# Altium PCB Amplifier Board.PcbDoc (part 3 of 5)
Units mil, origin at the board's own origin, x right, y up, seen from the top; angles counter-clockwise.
Board outline 6000 x 4000 mil, 6 copper layers (Top Layer, GND, VCC, InternalPlane3, InternalPlane4, Bottom Layer); 880 components, 519 nets, 2020 pads, 372 vias.
Unrouted connection lines stored in the file: 585.
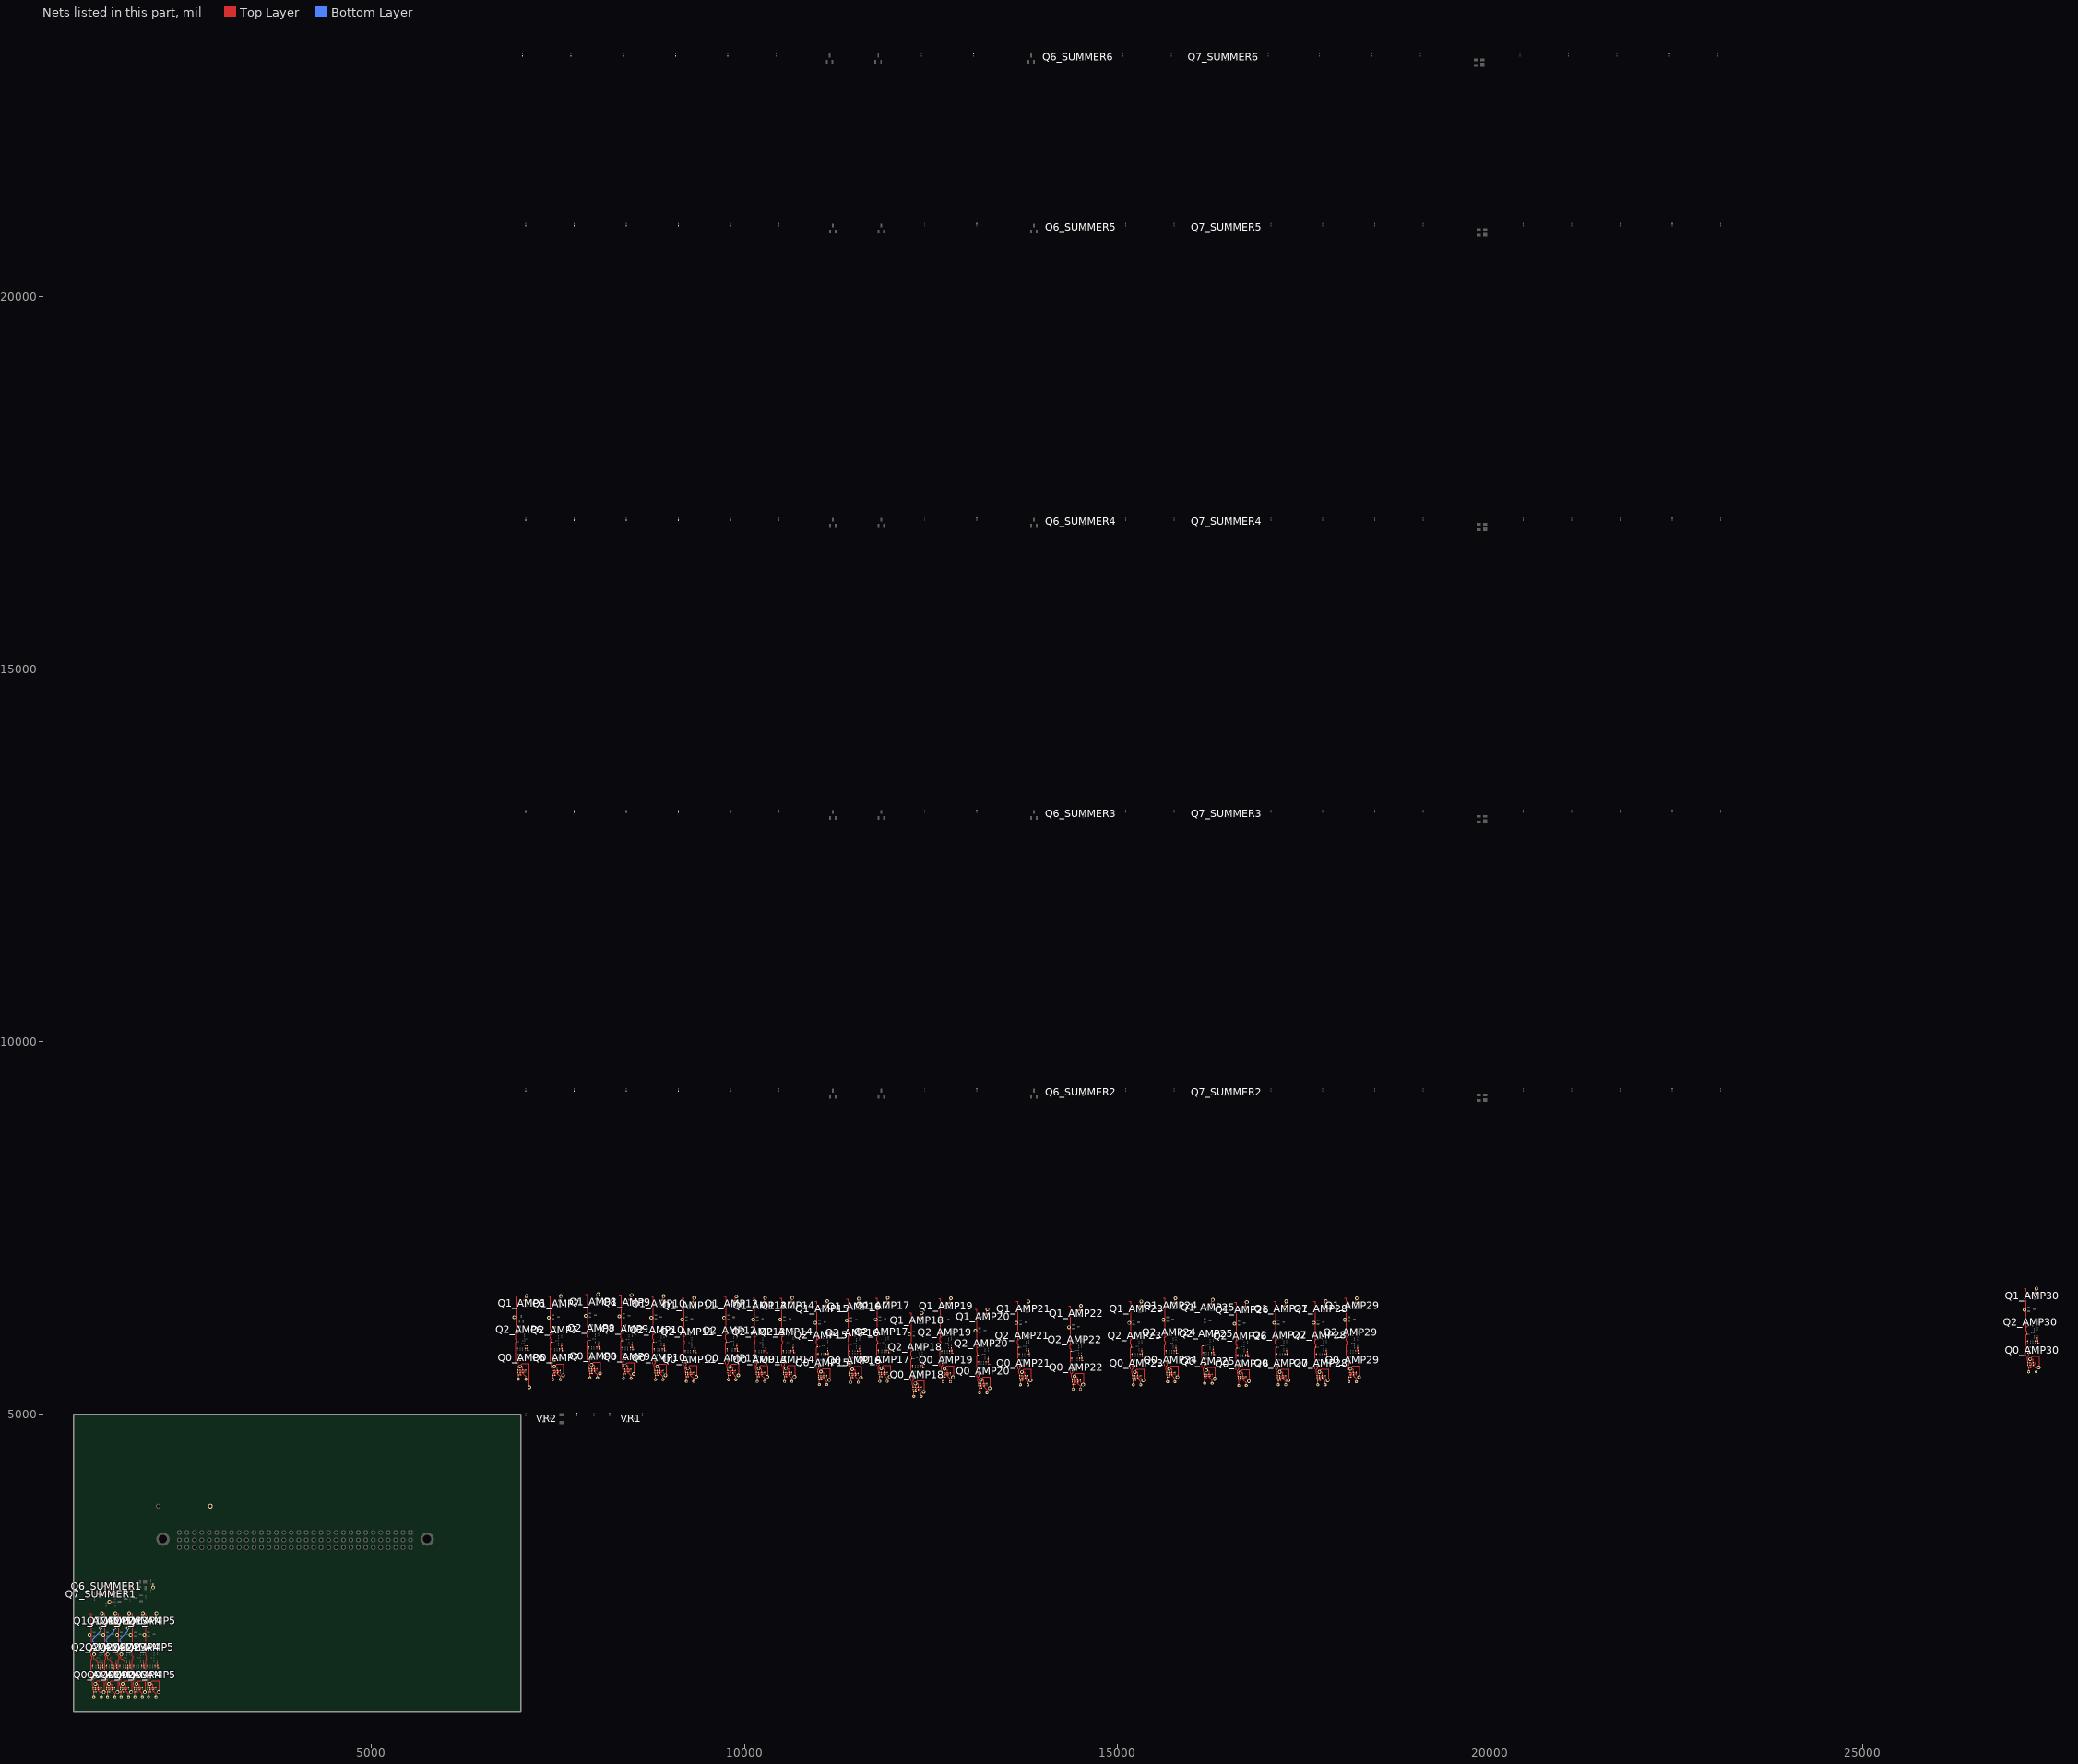
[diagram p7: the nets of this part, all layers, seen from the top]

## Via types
v1: diameter 50, hole 28, Top Layer to Bottom Layer, 371 vias
v2: diameter 50, hole 28, Top Layer to Bottom Layer, tented top, 1 vias

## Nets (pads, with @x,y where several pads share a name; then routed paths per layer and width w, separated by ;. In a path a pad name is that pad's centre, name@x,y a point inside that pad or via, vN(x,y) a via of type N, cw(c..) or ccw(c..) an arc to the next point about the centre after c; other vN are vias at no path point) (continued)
GND: C1_AMP1.2 C1_AMP2.2 C1_AMP3.2 C1_AMP4.2 C1_AMP5.2 C1_AMP6.2 C1_AMP7.2 C1_AMP8.2 C1_AMP9.2 C1_AMP10.2 C1_AMP11.2 C1_AMP12.2 C1_AMP13.2 C1_AMP14.2 C1_AMP15.2 C1_AMP16.2 C1_AMP17.2 C1_AMP18.2 C1_AMP19.2 C1_AMP20.2 C1_AMP21.2 C1_AMP22.2 C1_AMP23.2 C1_AMP24.2 C1_AMP25.2 C1_AMP26.2 C1_AMP27.2 C1_AMP28.2 C1_AMP29.2 C1_AMP30.2 C3_AMP1.1 C3_AMP2.1 C3_AMP3.1 C3_AMP4.1 C3_AMP5.1 C3_AMP6.1 C3_AMP7.1 C3_AMP8.1 C3_AMP9.1 C3_AMP10.1 C3_AMP11.1 C3_AMP12.1 C3_AMP13.1 C3_AMP14.1 C3_AMP15.1 C3_AMP16.1 C3_AMP17.1 C3_AMP18.1 C3_AMP19.1 C3_AMP20.1 C3_AMP21.1 C3_AMP22.1 C3_AMP23.1 C3_AMP24.1 C3_AMP25.1 C3_AMP26.1 C3_AMP27.1 C3_AMP28.1 C3_AMP29.1 C3_AMP30.1 CBi_AMP1.2 CBi_AMP2.2 CBi_AMP3.2 CBi_AMP4.2 CBi_AMP5.2 CBi_AMP6.2 CBi_AMP7.2 CBi_AMP8.2 CBi_AMP9.2 CBi_AMP10.2 CBi_AMP11.2 CBi_AMP12.2 CBi_AMP13.2 CBi_AMP14.2 CBi_AMP15.2 CBi_AMP16.2 CBi_AMP17.2 CBi_AMP18.2 CBi_AMP19.2 CBi_AMP20.2 CBi_AMP21.2 CBi_AMP22.2 CBi_AMP23.2 CBi_AMP24.2 CBi_AMP25.2 CBi_AMP26.2 CBi_AMP27.2 CBi_AMP28.2 CBi_AMP29.2 CBi_AMP30.2 CBi_SUMMER1.2 CBi_SUMMER2.2 CBi_SUMMER3.2 CBi_SUMMER4.2 CBi_SUMMER5.2 CBi_SUMMER6.2 CG_SUMMER1.2 CG_SUMMER2.2 CG_SUMMER3.2 CG_SUMMER4.2 CG_SUMMER5.2 CG_SUMMER6.2 D1.1 Q1_AMP1.2 Q1_AMP2.2 Q1_AMP3.2 Q1_AMP4.2 Q1_AMP5.2 Q1_AMP6.2 Q1_AMP7.2 Q1_AMP8.2 Q1_AMP9.2 Q1_AMP10.2 Q1_AMP11.2 Q1_AMP12.2 Q1_AMP13.2 Q1_AMP14.2 Q1_AMP15.2 Q1_AMP16.2 Q1_AMP17.2 Q1_AMP18.2 Q1_AMP19.2 Q1_AMP20.2 Q1_AMP21.2 Q1_AMP22.2 Q1_AMP23.2 Q1_AMP24.2 Q1_AMP25.2 Q1_AMP26.2 Q1_AMP27.2 Q1_AMP28.2 Q1_AMP29.2 Q1_AMP30.2 Q2_AMP1.3 Q2_AMP2.3 Q2_AMP3.3 Q2_AMP4.3 Q2_AMP5.3 Q2_AMP6.3 Q2_AMP7.3 Q2_AMP8.3 Q2_AMP9.3 Q2_AMP10.3 Q2_AMP11.3 Q2_AMP12.3 Q2_AMP13.3 Q2_AMP14.3 Q2_AMP15.3 Q2_AMP16.3 Q2_AMP17.3 Q2_AMP18.3 Q2_AMP19.3 Q2_AMP20.3 Q2_AMP21.3 Q2_AMP22.3 Q2_AMP23.3 Q2_AMP24.3 Q2_AMP25.3 Q2_AMP26.3 Q2_AMP27.3 Q2_AMP28.3 Q2_AMP29.3 Q2_AMP30.3 Q6_SUMMER1.3 Q6_SUMMER2.3 Q6_SUMMER3.3 Q6_SUMMER4.3 Q6_SUMMER5.3 Q6_SUMMER6.3 Q7_SUMMER1.3 Q7_SUMMER2.3 Q7_SUMMER3.3 Q7_SUMMER4.3 Q7_SUMMER5.3 Q7_SUMMER6.3 R1_AMP1.1 R1_AMP2.1 R1_AMP3.1 R1_AMP4.1 R1_AMP5.1 R1_AMP6.1 R1_AMP7.1 R1_AMP8.1 R1_AMP9.1 R1_AMP10.1 R1_AMP11.1 R1_AMP12.1 R1_AMP13.1 R1_AMP14.1 R1_AMP15.1 R1_AMP16.1 R1_AMP17.1 R1_AMP18.1 R1_AMP19.1 R1_AMP20.1 R1_AMP21.1 R1_AMP22.1 R1_AMP23.1 R1_AMP24.1 R1_AMP25.1 R1_AMP26.1 R1_AMP27.1 R1_AMP28.1 R1_AMP29.1 R1_AMP30.1 R3_AMP1.1 R3_AMP2.1 R3_AMP3.1 R3_AMP4.1 R3_AMP5.1 R3_AMP6.1 R3_AMP7.1 R3_AMP8.1 R3_AMP9.1 R3_AMP10.1 R3_AMP11.1 R3_AMP12.1 R3_AMP13.1 R3_AMP14.1 R3_AMP15.1 R3_AMP16.1 R3_AMP17.1 R3_AMP18.1 R3_AMP19.1 R3_AMP20.1 R3_AMP21.1 R3_AMP22.1 R3_AMP23.1 R3_AMP24.1 R3_AMP25.1 R3_AMP26.1 R3_AMP27.1 R3_AMP28.1 R3_AMP29.1 R3_AMP30.1 R9_SUMMER1.1 R9_SUMMER2.1 R9_SUMMER3.1 R9_SUMMER4.1 R9_SUMMER5.1 R9_SUMMER6.1 R12_SUMMER1.1 R12_SUMMER2.1 R12_SUMMER3.1 R12_SUMMER4.1 R12_SUMMER5.1 R12_SUMMER6.1 R14_SUMMER1.1 R14_SUMMER2.1 R14_SUMMER3.1 R14_SUMMER4.1 R14_SUMMER5.1 R14_SUMMER6.1 R17_SUMMER1.1 R17_SUMMER2.1 R17_SUMMER3.1 R17_SUMMER4.1 R17_SUMMER5.1 R17_SUMMER6.1 R19_AMP1.1 R19_AMP2.1 R19_AMP3.1 R19_AMP4.1 R19_AMP5.1 R19_AMP6.1 R19_AMP7.1 R19_AMP8.1 R19_AMP9.1 R19_AMP10.1 R19_AMP11.1 R19_AMP12.1 R19_AMP13.1 R19_AMP14.1 R19_AMP15.1 R19_AMP16.1 R19_AMP17.1 R19_AMP18.1 R19_AMP19.1 R19_AMP20.1 R19_AMP21.1 R19_AMP22.1 R19_AMP23.1 R19_AMP24.1 R19_AMP25.1 R19_AMP26.1 R19_AMP27.1 R19_AMP28.1 R19_AMP29.1 R19_AMP30.1 R22.2 R24.2 RC_SUMMER1.1 RC_SUMMER2.1 RC_SUMMER3.1 RC_SUMMER4.1 RC_SUMMER5.1 RC_SUMMER6.1 VR1.2 VR2.2 | length 48068.1
  Top Layer w7: 1216,2328 1242,2328 1242,1815 1241,1814 ; v1@1228,2039 v1@1241,2039 ; 1238,1420 1238,1701.78 R3_AMP1.1@1250.22,1714 ; 1238.22,1623.78 CBi_AMP1.2@1259,1623.78 ; R3_AMP1.1@1249,1715.22 1249,1745 1237.5,1756.5 1237.5,1806.5 1241,1814 ; 1275.41,1838.57 1250.84,1814 1241,1814 ; R19_AMP1.1@1302.78,1269 1302.78,1280.22 1294,1289 R1_AMP1.1@1294,1304 1314.59,1304 1314.59,1328.37 1317.78,1331.56 C1_AMP1.2@1334,1331.56 1334,1371.56 1324,1381.56 v1(1294,1381.56) 1294,1391 1324,1421 1419,1421 1419,1280 v1(1408,1269) ; Q1_AMP1.2@1370.34,2266.4 1370.34,2317.34 v1(1381,2328) ; C3_AMP1.1@1395,1596.22 1417.22,1596.22 ; v1@1399,2328 1425,2328 1425,1815 1424,1814 ; 1410.43,2559.41 1421.41,2559.41 1463,2601 v1(1543,2601) ; v1@1411,2039 v1@1424,2039 ; 1421,1420 1421,1701.78 R3_AMP2.1@1433.22,1714 ; 1421.22,1623.78 CBi_AMP2.2@1442,1623.78 ; R3_AMP2.1@1432,1715.22 1432,1745 1420.5,1756.5 1420.5,1806.5 1424,1814 ; R9_SUMMER1.1@1435,2453.78 1453.78,2453.78 v1(1484,2484) R12_SUMMER1.1@1535.22,2484 ; 1458.41,1838.57 1433.84,1814 1424,1814 ; 1480.43,2664.41 1480.43,2656.32 1498.54,2638.22 RC_SUMMER1.1@1524,2638.22 1524,2620 v1(1543,2601) ; R19_AMP2.1@1485.78,1269 1485.78,1280.22 1477,1289 R1_AMP2.1@1477,1304 1497.59,1304 1497.59,1328.37 1500.78,1331.56 C1_AMP2.2@1517,1331.56 1517,1371.56 1507,1381.56 v1(1477,1381.56) 1477,1391 1507,1421 1602,1421 1602,1280 v1(1591,1269) ; CBi_SUMMER1.2@1536.22,2555 1536.22,2594.22 v1(1543,2601) ; Q1_AMP2.2@1553.34,2266.4 1553.34,2317.34 v1(1564,2328) ; C3_AMP2.1@1578,1596.22 1600.22,1596.22 ; v1@1582,2328 1608,2328 1608,1815 1607,1814 ; v1@1594,2039 v1@1607,2039 ; 1604,1420 1604,1701.78 R3_AMP3.1@1616.22,1714 ; 1604.22,1623.78 CBi_AMP3.2@1625,1623.78 ; R3_AMP3.1@1615,1715.22 1615,1745 1603.5,1756.5 1603.5,1806.5 1607,1814 ; 1641.41,1838.57 1616.84,1814 1607,1814 ; R19_AMP3.1@1668.78,1269 1668.78,1280.22 1660,1289 R1_AMP3.1@1660,1304 1680.59,1304 1680.59,1328.37 1683.78,1331.56 C1_AMP3.2@1700,1331.56 1700,1371.56 1690,1381.56 v1(1660,1381.56) 1660,1391 1690,1421 1785,1421 1785,1280 v1(1774,1269) ; Q1_AMP3.2@1736.34,2266.4 1736.34,2317.34 v1(1747,2328) ; C3_AMP3.1@1761,1596.22 1783.22,1596.22 ; v1@1766,2328 1792,2328 1792,1815 1791,1814 ; R17_SUMMER1.1@1777.78,2627 R14_SUMMER1.1@1777.78,2702 ; v1@1778,2039 v1@1791,2039 ; 1788,1420 1788,1701.78 R3_AMP4.1@1800.22,1714 ; 1788.22,1623.78 CBi_AMP4.2@1809,1623.78 ; R3_AMP4.1@1799,1715.22 1799,1745 1787.5,1756.5 1787.5,1806.5 1791,1814 ; 1825.41,1838.57 1800.84,1814 1791,1814 ; R19_AMP4.1@1852.78,1269 1852.78,1280.22 1844,1289 R1_AMP4.1@1844,1304 1864.59,1304 1864.59,1328.37 1867.78,1331.56 C1_AMP4.2@1884,1331.56 1884,1371.56 1874,1381.56 v1(1844,1381.56) 1844,1391 1874,1421 1969,1421 1969,1280 v1(1958,1269) ; Q1_AMP4.2@1920.34,2266.4 1920.34,2317.34 v1(1931,2328) ; C3_AMP4.1@1945,1596.22 1967.22,1596.22 ; v1@1949,2328 1975,2328 1975,1815 1974,1814 ; v1@1961,2039 v1@1974,2039 ; 1971,1420 1971,1701.78 R3_AMP5.1@1983.22,1714 ; 1971.22,1623.78 CBi_AMP5.2@1992,1623.78 ; R3_AMP5.1@1982,1715.22 1982,1745 1970.5,1756.5 1970.5,1806.5 1974,1814 ; 2008.41,1838.57 1983.84,1814 1974,1814 ; R19_AMP5.1@2035.78,1269 2035.78,1280.22 2027,1289 R1_AMP5.1@2027,1304 2047.59,1304 2047.59,1328.37 2050.78,1331.56 C1_AMP5.2@2067,1331.56 2067,1371.56 2057,1381.56 v1(2027,1381.56) 2027,1391 2057,1421 2152,1421 2152,1280 v1(2141,1269) ; v1@2068.78,2675.22 CG_SUMMER1.2@2068.78,2720 ; Q1_AMP5.2@2103.34,2266.4 2103.34,2317.34 v1(2114,2328) ; C3_AMP5.1@2128,1596.22 2150.22,1596.22 ; 6912,6588 6938,6588 6938,6075 6937,6074 6933.5,6066.5 6933.5,6000 6945,5988.5 R3_AMP6.1@6945,5975.22 ; v1@6924,6299 v1@6937,6299 ; 6934,5680 6934,5961.78 R3_AMP6.1@6946.22,5974 ; 6934.22,5883.78 CBi_AMP6.2@6955,5883.78 ; 6940.57,6170.43 Q2_AMP6.3@6988,6170.43 ; R19_AMP6.1@6998.78,5529 6998.78,5540.22 6990,5549 R1_AMP6.1@6990,5564 7010.59,5564 7010.59,5588.37 7013.78,5591.56 C1_AMP6.2@7030,5591.56 7030,5631.56 7020,5641.56 v1(6990,5641.56) 6990,5651 7020,5681 7115,5681 v2@7115,5361 ; Q1_AMP6.2@7066.34,6526.4 7066.34,6577.34 v1(7077,6588) ; C3_AMP6.1@7091,5856.22 7113.22,5856.22 ; 7374,6583 7400,6583 7400,6070 7399,6069 ; v1@7386,6294 v1@7399,6294 ; 7396,5675 7396,5956.78 R3_AMP7.1@7408.22,5969 ; 7396.22,5878.78 CBi_AMP7.2@7417,5878.78 ; R3_AMP7.1@7407,5970.22 7407,6000 7395.5,6011.5 7395.5,6061.5 7399,6069 ; 7433.41,6093.57 7408.84,6069 7399,6069 ; R19_AMP7.1@7460.78,5524 7460.78,5535.22 7452,5544 R1_AMP7.1@7452,5559 7472.59,5559 7472.59,5583.37 7475.78,5586.56 C1_AMP7.2@7492,5586.56 7492,5626.56 7482,5636.56 v1(7452,5636.56) 7452,5646 7482,5676 7577,5676 7577,5535 v1(7566,5524) ; Q1_AMP7.2@7528.34,6521.4 7528.34,6572.34 v1(7539,6583) ; C3_AMP7.1@7553,5851.22 7575.22,5851.22 ; 7871,6607 7897,6607 7897,6094 7896,6093 ; v1@7883,6318 v1@7896,6318 ; 7893,5699 7893,5980.78 R3_AMP8.1@7905.22,5993 ; 7893.22,5902.78 CBi_AMP8.2@7914,5902.78 ; R3_AMP8.1@7904,5994.22 7904,6024 7892.5,6035.5 7892.5,6085.5 7896,6093 ; 7930.41,6117.57 7905.84,6093 7896,6093 ; R19_AMP8.1@7957.78,5548 7957.78,5559.22 7949,5568 R1_AMP8.1@7949,5583 7969.59,5583 7969.59,5607.37 7972.78,5610.56 C1_AMP8.2@7989,5610.56 7989,5650.56 7979,5660.56 v1(7949,5660.56) 7949,5670 7979,5700 8074,5700 8074,5559 v1(8063,5548) ; Q1_AMP8.2@8025.34,6545.4 8025.34,6596.34 v1(8036,6607) ; C3_AMP8.1@8050,5875.22 8072.22,5875.22 ; 8322,6600 8348,6600 8348,6087 8347,6086 ; v1@8334,6311 v1@8347,6311 ; 8344,5692 8344,5973.78 R3_AMP9.1@8356.22,5986 ; 8344.22,5895.78 CBi_AMP9.2@8365,5895.78 ; R3_AMP9.1@8355,5987.22 8355,6017 8343.5,6028.5 8343.5,6078.5 8347,6086 ; 8381.41,6110.57 8356.84,6086 8347,6086 ; R19_AMP9.1@8408.78,5541 8408.78,5552.22 8400,5561 R1_AMP9.1@8400,5576 8420.59,5576 8420.59,5600.37 8423.78,5603.56 C1_AMP9.2@8440,5603.56 8440,5643.56 8430,5653.56 v1(8400,5653.56) 8400,5663 8430,5693 8525,5693 8525,5552 v1(8514,5541) ; Q1_AMP9.2@8476.34,6538.4 8476.34,6589.34 v1(8487,6600) ; C3_AMP9.1@8501,5868.22 8523.22,5868.22 ; 8751,6583 8777,6583 8777,6070 8776,6069 ; v1@8763,6294 v1@8776,6294 ; 8773,5675 8773,5956.78 R3_AMP10.1@8785.22,5969 ; 8773.22,5878.78 CBi_AMP10.2@8794,5878.78 ; R3_AMP10.1@8784,5970.22 8784,6000 8772.5,6011.5 8772.5,6061.5 8776,6069 ; 8810.41,6093.57 8785.84,6069 8776,6069 ; R19_AMP10.1@8837.78,5524 8837.78,5535.22 8829,5544 R1_AMP10.1@8829,5559 8849.59,5559 8849.59,5583.37 8852.78,5586.56 C1_AMP10.2@8869,5586.56 8869,5626.56 8859,5636.56 v1(8829,5636.56) 8829,5646 8859,5676 8954,5676 8954,5535 v1(8943,5524) ; Q1_AMP10.2@8905.34,6521.4 8905.34,6572.34 v1(8916,6583) ; C3_AMP10.1@8930,5851.22 8952.22,5851.22 ; 9163,6559 9189,6559 9189,6046 9188,6045 ; v1@9175,6270 v1@9188,6270 ; 9185,5651 9185,5932.78 R3_AMP11.1@9197.22,5945 ; 9185.22,5854.78 CBi_AMP11.2@9206,5854.78 ; R3_AMP11.1@9196,5946.22 9196,5976 9184.5,5987.5 9184.5,6037.5 9188,6045 ; 9222.41,6069.57 9197.84,6045 9188,6045 ; R19_AMP11.1@9249.78,5500 9249.78,5511.22 9241,5520 R1_AMP11.1@9241,5535 9261.59,5535 9261.59,5559.37 9264.78,5562.56 C1_AMP11.2@9281,5562.56 9281,5602.56 9271,5612.56 v1(9241,5612.56) 9241,5622 9271,5652 9366,5652 9366,5511 v1(9355,5500) ; Q1_AMP11.2@9317.34,6497.4 9317.34,6548.34 v1(9328,6559) ; C3_AMP11.1@9342,5827.22 9364.22,5827.22 ; 9727,6581 9753,6581 9753,6068 9752,6067 ; v1@9739,6292 v1@9752,6292 ; 9749,5673 9749,5954.78 R3_AMP12.1@9761.22,5967 ; 9749.22,5876.78 CBi_AMP12.2@9770,5876.78 ; R3_AMP12.1@9760,5968.22 9760,5998 9748.5,6009.5 9748.5,6059.5 9752,6067 ; 9786.41,6091.57 9761.84,6067 9752,6067 ; R19_AMP12.1@9813.78,5522 9813.78,5533.22 9805,5542 R1_AMP12.1@9805,5557 9825.59,5557 9825.59,5581.37 9828.78,5584.56 C1_AMP12.2@9845,5584.56 9845,5624.56 9835,5634.56 v1(9805,5634.56) 9805,5644 9835,5674 9930,5674 9930,5533 v1(9919,5522) ; Q1_AMP12.2@9881.34,6519.4 9881.34,6570.34 v1(9892,6581) ; C3_AMP12.1@9906,5849.22 9928.22,5849.22 ; 10114,6559 10140,6559 10140,6046 10139,6045 ; v1@10126,6270 v1@10139,6270 ; 10136,5651 10136,5932.78 R3_AMP13.1@10148.22,5945 ; 10136.22,5854.78 CBi_AMP13.2@10157,5854.78 ; R3_AMP13.1@10147,5946.22 10147,5976 10135.5,5987.5 10135.5,6037.5 10139,6045 ; 10173.41,6069.57 10148.84,6045 10139,6045 ; R19_AMP13.1@10200.78,5500 10200.78,5511.22 10192,5520 R1_AMP13.1@10192,5535 10212.59,5535 10212.59,5559.37 10215.78,5562.56 C1_AMP13.2@10232,5562.56 10232,5602.56 10222,5612.56 v1(10192,5612.56) 10192,5622 10222,5652 10317,5652 10317,5511 v1(10306,5500) ; Q1_AMP13.2@10268.34,6497.4 10268.34,6548.34 v1(10279,6559) ; C3_AMP13.1@10293,5827.22 10315.22,5827.22 ; 10480,6559 10506,6559 10506,6046 10505,6045 ; v1@10492,6270 v1@10505,6270 ; 10502,5651 10502,5932.78 R3_AMP14.1@10514.22,5945 ; 10502.22,5854.78 CBi_AMP14.2@10523,5854.78 ; R3_AMP14.1@10513,5946.22 10513,5976 10501.5,5987.5 10501.5,6037.5 10505,6045 ; 10539.41,6069.57 10514.84,6045 10505,6045 ; R19_AMP14.1@10566.78,5500 10566.78,5511.22 10558,5520 R1_AMP14.1@10558,5535 10578.59,5535 10578.59,5559.37 10581.78,5562.56 C1_AMP14.2@10598,5562.56 10598,5602.56 10588,5612.56 v1(10558,5612.56) 10558,5622 10588,5652 10683,5652 10683,5511 v1(10672,5500) ; Q1_AMP14.2@10634.34,6497.4 10634.34,6548.34 v1(10645,6559) ; C3_AMP14.1@10659,5827.22 10681.22,5827.22 ; 10948,6516 10974,6516 10974,6003 10973,6002 ; v1@10960,6227 v1@10973,6227 ; 10970,5608 10970,5889.78 R3_AMP15.1@10982.22,5902 ; 10970.22,5811.78 CBi_AMP15.2@10991,5811.78 ; R3_AMP15.1@10981,5903.22 10981,5933 10969.5,5944.5 10969.5,5994.5 10973,6002 ; 11007.41,6026.57 10982.84,6002 10973,6002 ; R19_AMP15.1@11034.78,5457 11034.78,5468.22 11026,5477 R1_AMP15.1@11026,5492 11046.59,5492 11046.59,5516.37 11049.78,5519.56 C1_AMP15.2@11066,5519.56 11066,5559.56 11056,5569.56 v1(11026,5569.56) 11026,5579 11056,5609 11151,5609 11151,5468 v1(11140,5457) ; Q1_AMP15.2@11102.34,6454.4 11102.34,6505.34 v1(11113,6516) ; C3_AMP15.1@11127,5784.22 11149.22,5784.22 ; 11370,6548 11396,6548 11396,6035 11395,6034 ; v1@11382,6259 v1@11395,6259 ; 11392,5640 11392,5921.78 R3_AMP16.1@11404.22,5934 ; 11392.22,5843.78 CBi_AMP16.2@11413,5843.78 ; R3_AMP16.1@11403,5935.22 11403,5965 11391.5,5976.5 11391.5,6026.5 11395,6034 ; 11429.41,6058.57 11404.84,6034 11395,6034 ; R19_AMP16.1@11456.78,5489 11456.78,5500.22 11448,5509 R1_AMP16.1@11448,5524 11468.59,5524 11468.59,5548.37 11471.78,5551.56 C1_AMP16.2@11488,5551.56 11488,5591.56 11478,5601.56 v1(11448,5601.56) 11448,5611 11478,5641 11573,5641 11573,5500 v1(11562,5489) ; Q1_AMP16.2@11524.34,6486.4 11524.34,6537.34 v1(11535,6548) ; C3_AMP16.1@11549,5816.22 11571.22,5816.22 ; 11758,6560 11784,6560 11784,6047 11783,6046 ; v1@11770,6271 v1@11783,6271 ; 11780,5652 11780,5933.78 R3_AMP17.1@11792.22,5946 ; 11780.22,5855.78 CBi_AMP17.2@11801,5855.78 ; R3_AMP17.1@11791,5947.22 11791,5977 11779.5,5988.5 11779.5,6038.5 11783,6046 ; 11817.41,6070.57 11792.84,6046 11783,6046 ; R19_AMP17.1@11844.78,5501 11844.78,5512.22 11836,5521 R1_AMP17.1@11836,5536 11856.59,5536 11856.59,5560.37 11859.78,5563.56 C1_AMP17.2@11876,5563.56 11876,5603.56 11866,5613.56 v1(11836,5613.56) 11836,5623 11866,5653 11961,5653 11961,5512 v1(11950,5501) ; Q1_AMP17.2@11912.34,6498.4 11912.34,6549.34 v1(11923,6560) ; C3_AMP17.1@11937,5828.22 11959.22,5828.22 ; 12214,6358 12240,6358 12240,5845 12239,5844 ; v1@12226,6069 v1@12239,6069 ; 12236,5450 12236,5731.78 R3_AMP18.1@12248.22,5744 ; 12236.22,5653.78 CBi_AMP18.2@12257,5653.78 ; R3_AMP18.1@12247,5745.22 12247,5775 12235.5,5786.5 12235.5,5836.5 12239,5844 ; 12273.41,5868.57 12248.84,5844 12239,5844 ; R19_AMP18.1@12300.78,5299 12300.78,5310.22 12292,5319 R1_AMP18.1@12292,5334 12312.59,5334 12312.59,5358.37 12315.78,5361.56 C1_AMP18.2@12332,5361.56 12332,5401.56 12322,5411.56 v1(12292,5411.56) 12292,5421 12322,5451 12417,5451 12417,5310 v1(12406,5299) ; Q1_AMP18.2@12368.34,6296.4 12368.34,6347.34 v1(12379,6358) ; C3_AMP18.1@12393,5626.22 12415.22,5626.22 ; 12606,6554 12632,6554 12632,6041 12631,6040 ; v1@12618,6265 v1@12631,6265 ; 12628,5646 12628,5927.78 R3_AMP19.1@12640.22,5940 ; 12628.22,5849.78 CBi_AMP19.2@12649,5849.78 ; R3_AMP19.1@12639,5941.22 12639,5971 12627.5,5982.5 12627.5,6032.5 12631,6040 ; 12665.41,6064.57 12640.84,6040 12631,6040 ; R19_AMP19.1@12692.78,5495 12692.78,5506.22 12684,5515 R1_AMP19.1@12684,5530 12704.59,5530 12704.59,5554.37 12707.78,5557.56 C1_AMP19.2@12724,5557.56 12724,5597.56 12714,5607.56 v1(12684,5607.56) 12684,5617 12714,5647 12809,5647 12809,5506 v1(12798,5495) ; Q1_AMP19.2@12760.34,6492.4 12760.34,6543.34 v1(12771,6554) ; C3_AMP19.1@12785,5822.22 12807.22,5822.22 ; 13096,6407 13122,6407 13122,5894 13121,5893 ; v1@13108,6118 v1@13121,6118 ; 13118,5499 13118,5780.78 R3_AMP20.1@13130.22,5793 ; 13118.22,5702.78 CBi_AMP20.2@13139,5702.78 ; R3_AMP20.1@13129,5794.22 13129,5824 13117.5,5835.5 13117.5,5885.5 13121,5893 ; 13155.41,5917.57 13130.84,5893 13121,5893 ; R19_AMP20.1@13182.78,5348 13182.78,5359.22 13174,5368 R1_AMP20.1@13174,5383 13194.59,5383 13194.59,5407.37 13197.78,5410.56 C1_AMP20.2@13214,5410.56 13214,5450.56 13204,5460.56 v1(13174,5460.56) 13174,5470 13204,5500 13299,5500 13299,5359 v1(13288,5348) ; Q1_AMP20.2@13250.34,6345.4 13250.34,6396.34 v1(13261,6407) ; C3_AMP20.1@13275,5675.22 13297.22,5675.22 ; 13646,6513 13672,6513 13672,6000 13671,5999 ; v1@13658,6224 v1@13671,6224 ; 13668,5605 13668,5886.78 R3_AMP21.1@13680.22,5899 ; 13668.22,5808.78 CBi_AMP21.2@13689,5808.78 ; R3_AMP21.1@13679,5900.22 13679,5930 13667.5,5941.5 13667.5,5991.5 13671,5999 ; 13705.41,6023.57 13680.84,5999 13671,5999 ; R19_AMP21.1@13732.78,5454 13732.78,5465.22 13724,5474 R1_AMP21.1@13724,5489 13744.59,5489 13744.59,5513.37 13747.78,5516.56 C1_AMP21.2@13764,5516.56 13764,5556.56 13754,5566.56 v1(13724,5566.56) 13724,5576 13754,5606 13849,5606 13849,5465 v1(13838,5454) ; Q1_AMP21.2@13800.34,6451.4 13800.34,6502.34 v1(13811,6513) ; C3_AMP21.1@13825,5781.22 13847.22,5781.22 ; 14351,6455 14377,6455 14377,5942 14376,5941 ; v1@14363,6166 v1@14376,6166 ; 14373,5547 14373,5828.78 R3_AMP22.1@14385.22,5841 ; 14373.22,5750.78 CBi_AMP22.2@14394,5750.78 ; R3_AMP22.1@14384,5842.22 14384,5872 14372.5,5883.5 14372.5,5933.5 14376,5941 ; 14410.41,5965.57 14385.84,5941 14376,5941 ; R19_AMP22.1@14437.78,5396 14437.78,5407.22 14429,5416 R1_AMP22.1@14429,5431 14449.59,5431 14449.59,5455.37 14452.78,5458.56 C1_AMP22.2@14469,5458.56 14469,5498.56 14459,5508.56 v1(14429,5508.56) 14429,5518 14459,5548 14554,5548 14554,5407 v1(14543,5396) ; Q1_AMP22.2@14505.34,6393.4 14505.34,6444.34 v1(14516,6455) ; C3_AMP22.1@14530,5723.22 14552.22,5723.22 ; 15160,6513 15186,6513 15186,6000 15185,5999 ; v1@15172,6224 v1@15185,6224 ; 15182,5605 15182,5886.78 R3_AMP23.1@15194.22,5899 ; 15182.22,5808.78 CBi_AMP23.2@15203,5808.78 ; R3_AMP23.1@15193,5900.22 15193,5930 15181.5,5941.5 15181.5,5991.5 15185,5999 ; 15219.41,6023.57 15194.84,5999 15185,5999 ; R19_AMP23.1@15246.78,5454 15246.78,5465.22 15238,5474 R1_AMP23.1@15238,5489 15258.59,5489 15258.59,5513.37 15261.78,5516.56 C1_AMP23.2@15278,5516.56 15278,5556.56 15268,5566.56 v1(15238,5566.56) 15238,5576 15268,5606 15363,5606 15363,5465 v1(15352,5454) ; Q1_AMP23.2@15314.34,6451.4 15314.34,6502.34 v1(15325,6513) ; C3_AMP23.1@15339,5781.22 15361.22,5781.22 ; 15618,6555 15644,6555 15644,6042 15643,6041 ; v1@15630,6266 v1@15643,6266 ; 15640,5647 15640,5928.78 R3_AMP24.1@15652.22,5941 ; 15640.22,5850.78 CBi_AMP24.2@15661,5850.78 ; R3_AMP24.1@15651,5942.22 15651,5972 15639.5,5983.5 15639.5,6033.5 15643,6041 ; 15677.41,6065.57 15652.84,6041 15643,6041 ; R19_AMP24.1@15704.78,5496 15704.78,5507.22 15696,5516 R1_AMP24.1@15696,5531 15716.59,5531 15716.59,5555.37 15719.78,5558.56 C1_AMP24.2@15736,5558.56 15736,5598.56 15726,5608.56 v1(15696,5608.56) 15696,5618 15726,5648 15821,5648 15821,5507 v1(15810,5496) ; Q1_AMP24.2@15772.34,6493.4 15772.34,6544.34 v1(15783,6555) ; C3_AMP24.1@15797,5823.22 15819.22,5823.22 ; 16139,5626 16139,5907.78 R3_AMP25.1@16151.22,5920 ; 16139.22,5829.78 CBi_AMP25.2@16160,5829.78 ; R19_AMP25.1@16203.78,5475 16203.78,5486.22 16195,5495 R1_AMP25.1@16195,5510 16215.59,5510 16215.59,5534.37 16218.78,5537.56 C1_AMP25.2@16235,5537.56 16235,5577.56 16225,5587.56 v1(16195,5587.56) 16195,5597 16225,5627 16320,5627 16320,5486 v1(16309,5475) ; Q1_AMP25.2@16271.34,6472.4 16271.34,6523.34 v1(16282,6534) ; C3_AMP25.1@16296,5802.22 16318.22,5802.22 ; 16574,6503 16600,6503 16600,5990 16599,5989 ; v1@16586,6214 v1@16599,6214 ; 16596,5595 16596,5876.78 R3_AMP26.1@16608.22,5889 ; 16596.22,5798.78 CBi_AMP26.2@16617,5798.78 ; R3_AMP26.1@16607,5890.22 16607,5920 16595.5,5931.5 16595.5,5981.5 16599,5989 ; 16633.41,6013.57 16608.84,5989 16599,5989 ; R19_AMP26.1@16660.78,5444 16660.78,5455.22 16652,5464 R1_AMP26.1@16652,5479 16672.59,5479 16672.59,5503.37 16675.78,5506.56 C1_AMP26.2@16692,5506.56 16692,5546.56 16682,5556.56 v1(16652,5556.56) 16652,5566 16682,5596 16777,5596 16777,5455 v1(16766,5444) ; Q1_AMP26.2@16728.34,6441.4 16728.34,6492.34 v1(16739,6503) ; C3_AMP26.1@16753,5771.22 16775.22,5771.22 ; 17104,6514 17130,6514 17130,6001 17129,6000 ; v1@17116,6225 v1@17129,6225 ; 17126,5606 17126,5887.78 R3_AMP27.1@17138.22,5900 ; 17126.22,5809.78 CBi_AMP27.2@17147,5809.78 ; R3_AMP27.1@17137,5901.22 17137,5931 17125.5,5942.5 17125.5,5992.5 17129,6000 ; 17163.41,6024.57 17138.84,6000 17129,6000 ; R19_AMP27.1@17190.78,5455 17190.78,5466.22 17182,5475 R1_AMP27.1@17182,5490 17202.59,5490 17202.59,5514.37 17205.78,5517.56 C1_AMP27.2@17222,5517.56 17222,5557.56 17212,5567.56 v1(17182,5567.56) 17182,5577 17212,5607 17307,5607 17307,5466 v1(17296,5455) ; Q1_AMP27.2@17258.34,6452.4 17258.34,6503.34 v1(17269,6514) ; C3_AMP27.1@17283,5782.22 17305.22,5782.22 ; 17635,6514 17661,6514 17661,6001 17660,6000 ; v1@17647,6225 v1@17660,6225 ; 17657,5606 17657,5887.78 R3_AMP28.1@17669.22,5900 ; 17657.22,5809.78 CBi_AMP28.2@17678,5809.78 ; R3_AMP28.1@17668,5901.22 17668,5931 17656.5,5942.5 17656.5,5992.5 17660,6000 ; 17694.41,6024.57 17669.84,6000 17660,6000 ; R19_AMP28.1@17721.78,5455 17721.78,5466.22 17713,5475 R1_AMP28.1@17713,5490 17733.59,5490 17733.59,5514.37 17736.78,5517.56 C1_AMP28.2@17753,5517.56 17753,5557.56 17743,5567.56 v1(17713,5567.56) 17713,5577 17743,5607 17838,5607 17838,5466 v1(17827,5455) ; Q1_AMP28.2@17789.34,6452.4 17789.34,6503.34 v1(17800,6514) ; C3_AMP28.1@17814,5782.22 17836.22,5782.22 ; 18052,6555 18078,6555 18078,6042 18077,6041 ; v1@18064,6266 v1@18077,6266 ; 18074,5647 18074,5928.78 R3_AMP29.1@18086.22,5941 ; 18074.22,5850.78 CBi_AMP29.2@18095,5850.78 ; R3_AMP29.1@18085,5942.22 18085,5972 18073.5,5983.5 18073.5,6033.5 18077,6041 ; 18111.41,6065.57 18086.84,6041 18077,6041 ; R19_AMP29.1@18138.78,5496 18138.78,5507.22 18130,5516 R1_AMP29.1@18130,5531 18150.59,5531 18150.59,5555.37 18153.78,5558.56 C1_AMP29.2@18170,5558.56 18170,5598.56 18160,5608.56 v1(18130,5608.56) 18130,5618 18160,5648 18255,5648 18255,5507 v1(18244,5496) ; Q1_AMP29.2@18206.34,6493.4 18206.34,6544.34 v1(18217,6555) ; C3_AMP29.1@18231,5823.22 18253.22,5823.22 ; 27170,6687 27196,6687 27196,6174 27195,6173 ; v1@27182,6398 v1@27195,6398 ; 27192,5779 27192,6060.78 R3_AMP30.1@27204.22,6073 ; 27192.22,5982.78 CBi_AMP30.2@27213,5982.78 ; R3_AMP30.1@27203,6074.22 27203,6104 27191.5,6115.5 27191.5,6165.5 27195,6173 ; 27229.41,6197.57 27204.84,6173 27195,6173 ; R19_AMP30.1@27256.78,5628 27256.78,5639.22 27248,5648 R1_AMP30.1@27248,5663 27268.59,5663 27268.59,5687.37 27271.78,5690.56 C1_AMP30.2@27288,5690.56 27288,5730.56 27278,5740.56 v1(27248,5740.56) 27248,5750 27278,5780 27373,5780 27373,5639 v1(27362,5628) ; Q1_AMP30.2@27324.34,6625.4 27324.34,6676.34 v1(27335,6687) ; C3_AMP30.1@27349,5955.22 27371.22,5955.22
  other v1: 1218,2040 1401,2040 1584,2040 1768,2040 1951,2040 1777.78,2664 2070,2674 12216,6070 13098,6119 14353,6167 16576,6215 13648,6225 15162,6225 17106,6226 17637,6226 10950,6228 11372,6260 12608,6266 15620,6267 18054,6267 9165,6271 10116,6271 10482,6271 11760,6272 9729,6293 7376,6295 8753,6295 6914,6300 8324,6312 7873,6319 27172,6399
  other v2: 7116,5360
NetC1_AMP1_1: C1_AMP1.1 R18_AMP1.2 SIPM_AMP1.2 | length 176.2
  Top Layer w7: SIPM_AMP1.2@1374,1209 1374,1249 1334,1289 C1_AMP1.1@1334,1304 1350.22,1304 1354,1307.78 1354,1330.34 1355.22,1331.56 R18_AMP1.2@1374,1331.56
NetC1_AMP2_1: C1_AMP2.1 R18_AMP2.2 SIPM_AMP2.2 | length 176.2
  Top Layer w7: SIPM_AMP2.2@1557,1209 1557,1249 1517,1289 C1_AMP2.1@1517,1304 1533.22,1304 1537,1307.78 1537,1330.34 1538.22,1331.56 R18_AMP2.2@1557,1331.56
NetC1_AMP3_1: C1_AMP3.1 R18_AMP3.2 SIPM_AMP3.2 | length 176.2
  Top Layer w7: SIPM_AMP3.2@1740,1209 1740,1249 1700,1289 C1_AMP3.1@1700,1304 1716.22,1304 1720,1307.78 1720,1330.34 1721.22,1331.56 R18_AMP3.2@1740,1331.56
NetC1_AMP4_1: C1_AMP4.1 R18_AMP4.2 SIPM_AMP4.2 | length 176.2
  Top Layer w7: SIPM_AMP4.2@1924,1209 1924,1249 1884,1289 C1_AMP4.1@1884,1304 1900.22,1304 1904,1307.78 1904,1330.34 1905.22,1331.56 R18_AMP4.2@1924,1331.56
NetC1_AMP5_1: C1_AMP5.1 R18_AMP5.2 SIPM_AMP5.2 | length 176.2
  Top Layer w7: SIPM_AMP5.2@2107,1209 2107,1249 2067,1289 C1_AMP5.1@2067,1304 2083.22,1304 2087,1307.78 2087,1330.34 2088.22,1331.56 R18_AMP5.2@2107,1331.56
NetC1_AMP6_1: C1_AMP6.1 R18_AMP6.2 SIPM_AMP6.2 | length 176.2
  Top Layer w7: SIPM_AMP6.2@7070,5469 7070,5509 7030,5549 C1_AMP6.1@7030,5564 7046.22,5564 7050,5567.78 7050,5590.34 7051.22,5591.56 R18_AMP6.2@7070,5591.56
NetC1_AMP7_1: C1_AMP7.1 R18_AMP7.2 SIPM_AMP7.2 | length 176.2
  Top Layer w7: SIPM_AMP7.2@7532,5464 7532,5504 7492,5544 C1_AMP7.1@7492,5559 7508.22,5559 7512,5562.78 7512,5585.34 7513.22,5586.56 R18_AMP7.2@7532,5586.56
NetC1_AMP8_1: C1_AMP8.1 R18_AMP8.2 SIPM_AMP8.2 | length 176.2
  Top Layer w7: SIPM_AMP8.2@8029,5488 8029,5528 7989,5568 C1_AMP8.1@7989,5583 8005.22,5583 8009,5586.78 8009,5609.34 8010.22,5610.56 R18_AMP8.2@8029,5610.56
NetC1_AMP9_1: C1_AMP9.1 R18_AMP9.2 SIPM_AMP9.2 | length 176.2
  Top Layer w7: SIPM_AMP9.2@8480,5481 8480,5521 8440,5561 C1_AMP9.1@8440,5576 8456.22,5576 8460,5579.78 8460,5602.34 8461.22,5603.56 R18_AMP9.2@8480,5603.56
NetC1_AMP10_1: C1_AMP10.1 R18_AMP10.2 SIPM_AMP10.2 | length 176.2
  Top Layer w7: SIPM_AMP10.2@8909,5464 8909,5504 8869,5544 C1_AMP10.1@8869,5559 8885.22,5559 8889,5562.78 8889,5585.34 8890.22,5586.56 R18_AMP10.2@8909,5586.56
NetC1_AMP11_1: C1_AMP11.1 R18_AMP11.2 SIPM_AMP11.2 | length 176.2
  Top Layer w7: SIPM_AMP11.2@9321,5440 9321,5480 9281,5520 C1_AMP11.1@9281,5535 9297.22,5535 9301,5538.78 9301,5561.34 9302.22,5562.56 R18_AMP11.2@9321,5562.56
NetC1_AMP12_1: C1_AMP12.1 R18_AMP12.2 SIPM_AMP12.2 | length 176.2
  Top Layer w7: SIPM_AMP12.2@9885,5462 9885,5502 9845,5542 C1_AMP12.1@9845,5557 9861.22,5557 9865,5560.78 9865,5583.34 9866.22,5584.56 R18_AMP12.2@9885,5584.56
NetC1_AMP13_1: C1_AMP13.1 R18_AMP13.2 SIPM_AMP13.2 | length 176.2
  Top Layer w7: SIPM_AMP13.2@10272,5440 10272,5480 10232,5520 C1_AMP13.1@10232,5535 10248.22,5535 10252,5538.78 10252,5561.34 10253.22,5562.56 R18_AMP13.2@10272,5562.56
NetC1_AMP14_1: C1_AMP14.1 R18_AMP14.2 SIPM_AMP14.2 | length 176.2
  Top Layer w7: SIPM_AMP14.2@10638,5440 10638,5480 10598,5520 C1_AMP14.1@10598,5535 10614.22,5535 10618,5538.78 10618,5561.34 10619.22,5562.56 R18_AMP14.2@10638,5562.56
NetC1_AMP15_1: C1_AMP15.1 R18_AMP15.2 SIPM_AMP15.2 | length 176.2
  Top Layer w7: SIPM_AMP15.2@11106,5397 11106,5437 11066,5477 C1_AMP15.1@11066,5492 11082.22,5492 11086,5495.78 11086,5518.34 11087.22,5519.56 R18_AMP15.2@11106,5519.56
NetC1_AMP16_1: C1_AMP16.1 R18_AMP16.2 SIPM_AMP16.2 | length 176.2
  Top Layer w7: SIPM_AMP16.2@11528,5429 11528,5469 11488,5509 C1_AMP16.1@11488,5524 11504.22,5524 11508,5527.78 11508,5550.34 11509.22,5551.56 R18_AMP16.2@11528,5551.56
NetC1_AMP17_1: C1_AMP17.1 R18_AMP17.2 SIPM_AMP17.2 | length 176.2
  Top Layer w7: SIPM_AMP17.2@11916,5441 11916,5481 11876,5521 C1_AMP17.1@11876,5536 11892.22,5536 11896,5539.78 11896,5562.34 11897.22,5563.56 R18_AMP17.2@11916,5563.56
NetC1_AMP18_1: C1_AMP18.1 R18_AMP18.2 SIPM_AMP18.2 | length 176.2
  Top Layer w7: SIPM_AMP18.2@12372,5239 12372,5279 12332,5319 C1_AMP18.1@12332,5334 12348.22,5334 12352,5337.78 12352,5360.34 12353.22,5361.56 R18_AMP18.2@12372,5361.56
NetC1_AMP19_1: C1_AMP19.1 R18_AMP19.2 SIPM_AMP19.2 | length 176.2
  Top Layer w7: SIPM_AMP19.2@12764,5435 12764,5475 12724,5515 C1_AMP19.1@12724,5530 12740.22,5530 12744,5533.78 12744,5556.34 12745.22,5557.56 R18_AMP19.2@12764,5557.56
NetC1_AMP20_1: C1_AMP20.1 R18_AMP20.2 SIPM_AMP20.2 | length 176.2
  Top Layer w7: SIPM_AMP20.2@13254,5288 13254,5328 13214,5368 C1_AMP20.1@13214,5383 13230.22,5383 13234,5386.78 13234,5409.34 13235.22,5410.56 R18_AMP20.2@13254,5410.56
NetC1_AMP21_1: C1_AMP21.1 R18_AMP21.2 SIPM_AMP21.2 | length 176.2
  Top Layer w7: SIPM_AMP21.2@13804,5394 13804,5434 13764,5474 C1_AMP21.1@13764,5489 13780.22,5489 13784,5492.78 13784,5515.34 13785.22,5516.56 R18_AMP21.2@13804,5516.56
NetC1_AMP22_1: C1_AMP22.1 R18_AMP22.2 SIPM_AMP22.2 | length 176.2
  Top Layer w7: SIPM_AMP22.2@14509,5336 14509,5376 14469,5416 C1_AMP22.1@14469,5431 14485.22,5431 14489,5434.78 14489,5457.34 14490.22,5458.56 R18_AMP22.2@14509,5458.56
NetC1_AMP23_1: C1_AMP23.1 R18_AMP23.2 SIPM_AMP23.2 | length 176.2
  Top Layer w7: SIPM_AMP23.2@15318,5394 15318,5434 15278,5474 C1_AMP23.1@15278,5489 15294.22,5489 15298,5492.78 15298,5515.34 15299.22,5516.56 R18_AMP23.2@15318,5516.56
NetC1_AMP24_1: C1_AMP24.1 R18_AMP24.2 SIPM_AMP24.2 | length 176.2
  Top Layer w7: SIPM_AMP24.2@15776,5436 15776,5476 15736,5516 C1_AMP24.1@15736,5531 15752.22,5531 15756,5534.78 15756,5557.34 15757.22,5558.56 R18_AMP24.2@15776,5558.56
NetC1_AMP25_1: C1_AMP25.1 R18_AMP25.2 SIPM_AMP25.2 | length 176.2
  Top Layer w7: SIPM_AMP25.2@16275,5415 16275,5455 16235,5495 C1_AMP25.1@16235,5510 16251.22,5510 16255,5513.78 16255,5536.34 16256.22,5537.56 R18_AMP25.2@16275,5537.56
NetC1_AMP26_1: C1_AMP26.1 R18_AMP26.2 SIPM_AMP26.2 | length 176.2
  Top Layer w7: SIPM_AMP26.2@16732,5384 16732,5424 16692,5464 C1_AMP26.1@16692,5479 16708.22,5479 16712,5482.78 16712,5505.34 16713.22,5506.56 R18_AMP26.2@16732,5506.56
NetC1_AMP27_1: C1_AMP27.1 R18_AMP27.2 SIPM_AMP27.2 | length 176.2
  Top Layer w7: SIPM_AMP27.2@17262,5395 17262,5435 17222,5475 C1_AMP27.1@17222,5490 17238.22,5490 17242,5493.78 17242,5516.34 17243.22,5517.56 R18_AMP27.2@17262,5517.56
NetC1_AMP28_1: C1_AMP28.1 R18_AMP28.2 SIPM_AMP28.2 | length 176.2
  Top Layer w7: SIPM_AMP28.2@17793,5395 17793,5435 17753,5475 C1_AMP28.1@17753,5490 17769.22,5490 17773,5493.78 17773,5516.34 17774.22,5517.56 R18_AMP28.2@17793,5517.56
NetC1_AMP29_1: C1_AMP29.1 R18_AMP29.2 SIPM_AMP29.2 | length 176.2
  Top Layer w7: SIPM_AMP29.2@18210,5436 18210,5476 18170,5516 C1_AMP29.1@18170,5531 18186.22,5531 18190,5534.78 18190,5557.34 18191.22,5558.56 R18_AMP29.2@18210,5558.56
NetC1_AMP30_1: C1_AMP30.1 R18_AMP30.2 SIPM_AMP30.2 | length 176.2
  Top Layer w7: SIPM_AMP30.2@27328,5568 27328,5608 27288,5648 C1_AMP30.1@27288,5663 27304.22,5663 27308,5666.78 27308,5689.34 27309.22,5690.56 R18_AMP30.2@27328,5690.56
NetC2_AMP1_1: C2_AMP1.1 R19_AMP1.2 SIPM_AMP1.1 | length 86.3
  Top Layer w7: 1264,1291.88 1275.22,1280.66 SIPM_AMP1.1@1275.22,1210.22
NetC2_AMP1_2: C2_AMP1.2 Q0_AMP1.2 R1_AMP1.2 | length 177.4
  Top Layer w7: Q0_AMP1.2@1282.66,1464.16 1274,1455.5 1274,1431.56 1255.5,1413.06 1255.5,1365.93 1264,1357.43 C2_AMP1.2@1264,1331.56 R1_AMP1.2@1294,1331.56
NetC2_AMP2_1: C2_AMP2.1 R19_AMP2.2 SIPM_AMP2.1 | length 86.3
  Top Layer w7: 1447,1291.88 1458.22,1280.66 SIPM_AMP2.1@1458.22,1210.22
NetC2_AMP2_2: C2_AMP2.2 Q0_AMP2.2 R1_AMP2.2 | length 177.4
  Top Layer w7: Q0_AMP2.2@1465.66,1464.16 1457,1455.5 1457,1431.56 1438.5,1413.06 1438.5,1365.93 1447,1357.43 C2_AMP2.2@1447,1331.56 R1_AMP2.2@1477,1331.56
NetC2_AMP3_1: C2_AMP3.1 R19_AMP3.2 SIPM_AMP3.1 | length 86.3
  Top Layer w7: 1630,1291.88 1641.22,1280.66 SIPM_AMP3.1@1641.22,1210.22
NetC2_AMP3_2: C2_AMP3.2 Q0_AMP3.2 R1_AMP3.2 | length 177.4
  Top Layer w7: Q0_AMP3.2@1648.66,1464.16 1640,1455.5 1640,1431.56 1621.5,1413.06 1621.5,1365.93 1630,1357.43 C2_AMP3.2@1630,1331.56 R1_AMP3.2@1660,1331.56
NetC2_AMP4_1: C2_AMP4.1 R19_AMP4.2 SIPM_AMP4.1 | length 86.3
  Top Layer w7: 1814,1291.88 1825.22,1280.66 SIPM_AMP4.1@1825.22,1210.22
NetC2_AMP4_2: C2_AMP4.2 Q0_AMP4.2 R1_AMP4.2 | length 177.4
  Top Layer w7: Q0_AMP4.2@1832.66,1464.16 1824,1455.5 1824,1431.56 1805.5,1413.06 1805.5,1365.93 1814,1357.43 C2_AMP4.2@1814,1331.56 R1_AMP4.2@1844,1331.56
NetC2_AMP5_1: C2_AMP5.1 R19_AMP5.2 SIPM_AMP5.1 | length 86.3
  Top Layer w7: 1997,1291.88 2008.22,1280.66 SIPM_AMP5.1@2008.22,1210.22
NetC2_AMP5_2: C2_AMP5.2 Q0_AMP5.2 R1_AMP5.2 | length 177.4
  Top Layer w7: Q0_AMP5.2@2015.66,1464.16 2007,1455.5 2007,1431.56 1988.5,1413.06 1988.5,1365.93 1997,1357.43 C2_AMP5.2@1997,1331.56 R1_AMP5.2@2027,1331.56
NetC2_AMP6_1: C2_AMP6.1 R19_AMP6.2 SIPM_AMP6.1 | length 86.3
  Top Layer w7: 6960,5551.88 6971.22,5540.66 SIPM_AMP6.1@6971.22,5470.22
NetC2_AMP6_2: C2_AMP6.2 Q0_AMP6.2 R1_AMP6.2 | length 177.4
  Top Layer w7: Q0_AMP6.2@6978.66,5724.16 6970,5715.5 6970,5691.56 6951.5,5673.06 6951.5,5625.93 6960,5617.43 C2_AMP6.2@6960,5591.56 R1_AMP6.2@6990,5591.56
NetC2_AMP7_1: C2_AMP7.1 R19_AMP7.2 SIPM_AMP7.1 | length 86.3
  Top Layer w7: 7422,5546.88 7433.22,5535.66 SIPM_AMP7.1@7433.22,5465.22
NetC2_AMP7_2: C2_AMP7.2 Q0_AMP7.2 R1_AMP7.2 | length 177.4
  Top Layer w7: Q0_AMP7.2@7440.66,5719.16 7432,5710.5 7432,5686.56 7413.5,5668.06 7413.5,5620.93 7422,5612.43 C2_AMP7.2@7422,5586.56 R1_AMP7.2@7452,5586.56
NetC2_AMP8_1: C2_AMP8.1 R19_AMP8.2 SIPM_AMP8.1 | length 86.3
  Top Layer w7: 7919,5570.88 7930.22,5559.66 SIPM_AMP8.1@7930.22,5489.22
NetC2_AMP8_2: C2_AMP8.2 Q0_AMP8.2 R1_AMP8.2 | length 177.4
  Top Layer w7: Q0_AMP8.2@7937.66,5743.16 7929,5734.5 7929,5710.56 7910.5,5692.06 7910.5,5644.93 7919,5636.43 C2_AMP8.2@7919,5610.56 R1_AMP8.2@7949,5610.56
NetC2_AMP9_1: C2_AMP9.1 R19_AMP9.2 SIPM_AMP9.1 | length 86.3
  Top Layer w7: 8370,5563.88 8381.22,5552.66 SIPM_AMP9.1@8381.22,5482.22
NetC2_AMP9_2: C2_AMP9.2 Q0_AMP9.2 R1_AMP9.2 | length 177.4
  Top Layer w7: Q0_AMP9.2@8388.66,5736.16 8380,5727.5 8380,5703.56 8361.5,5685.06 8361.5,5637.93 8370,5629.43 C2_AMP9.2@8370,5603.56 R1_AMP9.2@8400,5603.56
NetC2_AMP10_1: C2_AMP10.1 R19_AMP10.2 SIPM_AMP10.1 | length 86.3
  Top Layer w7: 8799,5546.88 8810.22,5535.66 SIPM_AMP10.1@8810.22,5465.22
NetC2_AMP10_2: C2_AMP10.2 Q0_AMP10.2 R1_AMP10.2 | length 177.4
  Top Layer w7: Q0_AMP10.2@8817.66,5719.16 8809,5710.5 8809,5686.56 8790.5,5668.06 8790.5,5620.93 8799,5612.43 C2_AMP10.2@8799,5586.56 R1_AMP10.2@8829,5586.56
NetC2_AMP11_1: C2_AMP11.1 R19_AMP11.2 SIPM_AMP11.1 | length 86.3
  Top Layer w7: 9211,5522.88 9222.22,5511.66 SIPM_AMP11.1@9222.22,5441.22
NetC2_AMP11_2: C2_AMP11.2 Q0_AMP11.2 R1_AMP11.2 | length 177.4
  Top Layer w7: Q0_AMP11.2@9229.66,5695.16 9221,5686.5 9221,5662.56 9202.5,5644.06 9202.5,5596.93 9211,5588.43 C2_AMP11.2@9211,5562.56 R1_AMP11.2@9241,5562.56
NetC2_AMP12_1: C2_AMP12.1 R19_AMP12.2 SIPM_AMP12.1 | length 86.3
  Top Layer w7: 9775,5544.88 9786.22,5533.66 SIPM_AMP12.1@9786.22,5463.22
NetC2_AMP12_2: C2_AMP12.2 Q0_AMP12.2 R1_AMP12.2 | length 177.4
  Top Layer w7: Q0_AMP12.2@9793.66,5717.16 9785,5708.5 9785,5684.56 9766.5,5666.06 9766.5,5618.93 9775,5610.43 C2_AMP12.2@9775,5584.56 R1_AMP12.2@9805,5584.56
NetC2_AMP13_1: C2_AMP13.1 R19_AMP13.2 SIPM_AMP13.1 | length 86.3
  Top Layer w7: 10162,5522.88 10173.22,5511.66 SIPM_AMP13.1@10173.22,5441.22
NetC2_AMP13_2: C2_AMP13.2 Q0_AMP13.2 R1_AMP13.2 | length 177.4
  Top Layer w7: Q0_AMP13.2@10180.66,5695.16 10172,5686.5 10172,5662.56 10153.5,5644.06 10153.5,5596.93 10162,5588.43 C2_AMP13.2@10162,5562.56 R1_AMP13.2@10192,5562.56
NetC2_AMP14_1: C2_AMP14.1 R19_AMP14.2 SIPM_AMP14.1 | length 86.3
  Top Layer w7: 10528,5522.88 10539.22,5511.66 SIPM_AMP14.1@10539.22,5441.22
NetC2_AMP14_2: C2_AMP14.2 Q0_AMP14.2 R1_AMP14.2 | length 177.4
  Top Layer w7: Q0_AMP14.2@10546.66,5695.16 10538,5686.5 10538,5662.56 10519.5,5644.06 10519.5,5596.93 10528,5588.43 C2_AMP14.2@10528,5562.56 R1_AMP14.2@10558,5562.56
NetC2_AMP15_1: C2_AMP15.1 R19_AMP15.2 SIPM_AMP15.1 | length 86.3
  Top Layer w7: 10996,5479.88 11007.22,5468.66 SIPM_AMP15.1@11007.22,5398.22
NetC2_AMP15_2: C2_AMP15.2 Q0_AMP15.2 R1_AMP15.2 | length 177.4
  Top Layer w7: Q0_AMP15.2@11014.66,5652.16 11006,5643.5 11006,5619.56 10987.5,5601.06 10987.5,5553.93 10996,5545.43 C2_AMP15.2@10996,5519.56 R1_AMP15.2@11026,5519.56
NetC2_AMP16_1: C2_AMP16.1 R19_AMP16.2 SIPM_AMP16.1 | length 86.3
  Top Layer w7: 11418,5511.88 11429.22,5500.66 SIPM_AMP16.1@11429.22,5430.22
NetC2_AMP16_2: C2_AMP16.2 Q0_AMP16.2 R1_AMP16.2 | length 177.4
  Top Layer w7: Q0_AMP16.2@11436.66,5684.16 11428,5675.5 11428,5651.56 11409.5,5633.06 11409.5,5585.93 11418,5577.43 C2_AMP16.2@11418,5551.56 R1_AMP16.2@11448,5551.56
NetC2_AMP17_1: C2_AMP17.1 R19_AMP17.2 SIPM_AMP17.1 | length 86.3
  Top Layer w7: 11806,5523.88 11817.22,5512.66 SIPM_AMP17.1@11817.22,5442.22
NetC2_AMP17_2: C2_AMP17.2 Q0_AMP17.2 R1_AMP17.2 | length 177.4
  Top Layer w7: Q0_AMP17.2@11824.66,5696.16 11816,5687.5 11816,5663.56 11797.5,5645.06 11797.5,5597.93 11806,5589.43 C2_AMP17.2@11806,5563.56 R1_AMP17.2@11836,5563.56
NetC2_AMP18_1: C2_AMP18.1 R19_AMP18.2 SIPM_AMP18.1 | length 86.3
  Top Layer w7: 12262,5321.88 12273.22,5310.66 SIPM_AMP18.1@12273.22,5240.22
NetC2_AMP18_2: C2_AMP18.2 Q0_AMP18.2 R1_AMP18.2 | length 177.4
  Top Layer w7: Q0_AMP18.2@12280.66,5494.16 12272,5485.5 12272,5461.56 12253.5,5443.06 12253.5,5395.93 12262,5387.43 C2_AMP18.2@12262,5361.56 R1_AMP18.2@12292,5361.56
NetC2_AMP19_1: C2_AMP19.1 R19_AMP19.2 SIPM_AMP19.1 | length 86.3
  Top Layer w7: 12654,5517.88 12665.22,5506.66 SIPM_AMP19.1@12665.22,5436.22
NetC2_AMP19_2: C2_AMP19.2 Q0_AMP19.2 R1_AMP19.2 | length 177.4
  Top Layer w7: Q0_AMP19.2@12672.66,5690.16 12664,5681.5 12664,5657.56 12645.5,5639.06 12645.5,5591.93 12654,5583.43 C2_AMP19.2@12654,5557.56 R1_AMP19.2@12684,5557.56
NetC2_AMP20_1: C2_AMP20.1 R19_AMP20.2 SIPM_AMP20.1 | length 86.3
  Top Layer w7: 13144,5370.88 13155.22,5359.66 SIPM_AMP20.1@13155.22,5289.22
NetC2_AMP20_2: C2_AMP20.2 Q0_AMP20.2 R1_AMP20.2 | length 177.4
  Top Layer w7: Q0_AMP20.2@13162.66,5543.16 13154,5534.5 13154,5510.56 13135.5,5492.06 13135.5,5444.93 13144,5436.43 C2_AMP20.2@13144,5410.56 R1_AMP20.2@13174,5410.56
NetC2_AMP21_1: C2_AMP21.1 R19_AMP21.2 SIPM_AMP21.1 | length 86.3
  Top Layer w7: 13694,5476.88 13705.22,5465.66 SIPM_AMP21.1@13705.22,5395.22
NetC2_AMP21_2: C2_AMP21.2 Q0_AMP21.2 R1_AMP21.2 | length 177.4
  Top Layer w7: Q0_AMP21.2@13712.66,5649.16 13704,5640.5 13704,5616.56 13685.5,5598.06 13685.5,5550.93 13694,5542.43 C2_AMP21.2@13694,5516.56 R1_AMP21.2@13724,5516.56
NetC2_AMP22_1: C2_AMP22.1 R19_AMP22.2 SIPM_AMP22.1 | length 86.3
  Top Layer w7: 14399,5418.88 14410.22,5407.66 SIPM_AMP22.1@14410.22,5337.22
NetC2_AMP22_2: C2_AMP22.2 Q0_AMP22.2 R1_AMP22.2 | length 177.4
  Top Layer w7: Q0_AMP22.2@14417.66,5591.16 14409,5582.5 14409,5558.56 14390.5,5540.06 14390.5,5492.93 14399,5484.43 C2_AMP22.2@14399,5458.56 R1_AMP22.2@14429,5458.56
NetC2_AMP23_1: C2_AMP23.1 R19_AMP23.2 SIPM_AMP23.1 | length 86.3
  Top Layer w7: 15208,5476.88 15219.22,5465.66 SIPM_AMP23.1@15219.22,5395.22
NetC2_AMP23_2: C2_AMP23.2 Q0_AMP23.2 R1_AMP23.2 | length 177.4
  Top Layer w7: Q0_AMP23.2@15226.66,5649.16 15218,5640.5 15218,5616.56 15199.5,5598.06 15199.5,5550.93 15208,5542.43 C2_AMP23.2@15208,5516.56 R1_AMP23.2@15238,5516.56
NetC2_AMP24_1: C2_AMP24.1 R19_AMP24.2 SIPM_AMP24.1 | length 86.3
  Top Layer w7: 15666,5518.88 15677.22,5507.66 SIPM_AMP24.1@15677.22,5437.22
NetC2_AMP24_2: C2_AMP24.2 Q0_AMP24.2 R1_AMP24.2 | length 177.4
  Top Layer w7: Q0_AMP24.2@15684.66,5691.16 15676,5682.5 15676,5658.56 15657.5,5640.06 15657.5,5592.93 15666,5584.43 C2_AMP24.2@15666,5558.56 R1_AMP24.2@15696,5558.56
NetC2_AMP25_1: C2_AMP25.1 R19_AMP25.2 SIPM_AMP25.1 | length 86.3
  Top Layer w7: 16165,5497.88 16176.22,5486.66 SIPM_AMP25.1@16176.22,5416.22
NetC2_AMP25_2: C2_AMP25.2 Q0_AMP25.2 R1_AMP25.2 | length 177.4
  Top Layer w7: Q0_AMP25.2@16183.66,5670.16 16175,5661.5 16175,5637.56 16156.5,5619.06 16156.5,5571.93 16165,5563.43 C2_AMP25.2@16165,5537.56 R1_AMP25.2@16195,5537.56
NetC2_AMP26_1: C2_AMP26.1 R19_AMP26.2 SIPM_AMP26.1 | length 86.3
  Top Layer w7: 16622,5466.88 16633.22,5455.66 SIPM_AMP26.1@16633.22,5385.22
NetC2_AMP26_2: C2_AMP26.2 Q0_AMP26.2 R1_AMP26.2 | length 177.4
  Top Layer w7: Q0_AMP26.2@16640.66,5639.16 16632,5630.5 16632,5606.56 16613.5,5588.06 16613.5,5540.93 16622,5532.43 C2_AMP26.2@16622,5506.56 R1_AMP26.2@16652,5506.56
NetC2_AMP27_1: C2_AMP27.1 R19_AMP27.2 SIPM_AMP27.1 | length 86.3
  Top Layer w7: 17152,5477.88 17163.22,5466.66 SIPM_AMP27.1@17163.22,5396.22
NetC2_AMP27_2: C2_AMP27.2 Q0_AMP27.2 R1_AMP27.2 | length 177.4
  Top Layer w7: Q0_AMP27.2@17170.66,5650.16 17162,5641.5 17162,5617.56 17143.5,5599.06 17143.5,5551.93 17152,5543.43 C2_AMP27.2@17152,5517.56 R1_AMP27.2@17182,5517.56
NetC2_AMP28_1: C2_AMP28.1 R19_AMP28.2 SIPM_AMP28.1 | length 86.3
  Top Layer w7: 17683,5477.88 17694.22,5466.66 SIPM_AMP28.1@17694.22,5396.22
NetC2_AMP28_2: C2_AMP28.2 Q0_AMP28.2 R1_AMP28.2 | length 177.4
  Top Layer w7: Q0_AMP28.2@17701.66,5650.16 17693,5641.5 17693,5617.56 17674.5,5599.06 17674.5,5551.93 17683,5543.43 C2_AMP28.2@17683,5517.56 R1_AMP28.2@17713,5517.56
NetC2_AMP29_1: C2_AMP29.1 R19_AMP29.2 SIPM_AMP29.1 | length 86.3
  Top Layer w7: 18100,5518.88 18111.22,5507.66 SIPM_AMP29.1@18111.22,5437.22
NetC2_AMP29_2: C2_AMP29.2 Q0_AMP29.2 R1_AMP29.2 | length 177.4
  Top Layer w7: Q0_AMP29.2@18118.66,5691.16 18110,5682.5 18110,5658.56 18091.5,5640.06 18091.5,5592.93 18100,5584.43 C2_AMP29.2@18100,5558.56 R1_AMP29.2@18130,5558.56
NetC2_AMP30_1: C2_AMP30.1 R19_AMP30.2 SIPM_AMP30.1 | length 86.3
  Top Layer w7: 27218,5650.88 27229.22,5639.66 SIPM_AMP30.1@27229.22,5569.22
NetC2_AMP30_2: C2_AMP30.2 Q0_AMP30.2 R1_AMP30.2 | length 177.4
  Top Layer w7: Q0_AMP30.2@27236.66,5823.16 27228,5814.5 27228,5790.56 27209.5,5772.06 27209.5,5724.93 27218,5716.43 C2_AMP30.2@27218,5690.56 R1_AMP30.2@27248,5690.56
NetC3_AMP1_2: C3_AMP1.2 R6_AMP1.2 R20_AMP1.1 | length 75.9
  Top Layer w7: R6_AMP1.2@1363,1623.78 C3_AMP1.2@1395,1623.78 1395,1641 1389,1647 R20_AMP1.1@1389,1665.22
NetC3_AMP2_2: C3_AMP2.2 R6_AMP2.2 R20_AMP2.1 | length 75.9
  Top Layer w7: R6_AMP2.2@1546,1623.78 C3_AMP2.2@1578,1623.78 1578,1641 1572,1647 R20_AMP2.1@1572,1665.22
NetC3_AMP3_2: C3_AMP3.2 R6_AMP3.2 R20_AMP3.1 | length 75.9
  Top Layer w7: R6_AMP3.2@1729,1623.78 C3_AMP3.2@1761,1623.78 1761,1641 1755,1647 R20_AMP3.1@1755,1665.22
NetC3_AMP4_2: C3_AMP4.2 R6_AMP4.2 R20_AMP4.1 | length 75.9
  Top Layer w7: R6_AMP4.2@1913,1623.78 C3_AMP4.2@1945,1623.78 1945,1641 1939,1647 R20_AMP4.1@1939,1665.22
NetC3_AMP5_2: C3_AMP5.2 R6_AMP5.2 R20_AMP5.1 | length 75.9
  Top Layer w7: R6_AMP5.2@2096,1623.78 C3_AMP5.2@2128,1623.78 2128,1641 2122,1647 R20_AMP5.1@2122,1665.22
NetC3_AMP6_2: C3_AMP6.2 R6_AMP6.2 R20_AMP6.1 | length 66.4
  Top Layer w7: R6_AMP6.2@7059,5883.78 C3_AMP6.2@7091,5883.78 7091,5895.59 7098.78,5903.37 7098.78,5915
NetC3_AMP7_2: C3_AMP7.2 R6_AMP7.2 R20_AMP7.1 | length 75.9
  Top Layer w7: R6_AMP7.2@7521,5878.78 C3_AMP7.2@7553,5878.78 7553,5896 7547,5902 R20_AMP7.1@7547,5920.22
NetC3_AMP8_2: C3_AMP8.2 R6_AMP8.2 R20_AMP8.1 | length 75.9
  Top Layer w7: R6_AMP8.2@8018,5902.78 C3_AMP8.2@8050,5902.78 8050,5920 8044,5926 R20_AMP8.1@8044,5944.22
NetC3_AMP9_2: C3_AMP9.2 R6_AMP9.2 R20_AMP9.1 | length 75.9
  Top Layer w7: R6_AMP9.2@8469,5895.78 C3_AMP9.2@8501,5895.78 8501,5913 8495,5919 R20_AMP9.1@8495,5937.22
NetC3_AMP10_2: C3_AMP10.2 R6_AMP10.2 R20_AMP10.1 | length 75.9
  Top Layer w7: R6_AMP10.2@8898,5878.78 C3_AMP10.2@8930,5878.78 8930,5896 8924,5902 R20_AMP10.1@8924,5920.22
NetC3_AMP11_2: C3_AMP11.2 R6_AMP11.2 R20_AMP11.1 | length 75.9
  Top Layer w7: R6_AMP11.2@9310,5854.78 C3_AMP11.2@9342,5854.78 9342,5872 9336,5878 R20_AMP11.1@9336,5896.22
NetC3_AMP12_2: C3_AMP12.2 R6_AMP12.2 R20_AMP12.1 | length 75.9
  Top Layer w7: R6_AMP12.2@9874,5876.78 C3_AMP12.2@9906,5876.78 9906,5894 9900,5900 R20_AMP12.1@9900,5918.22
NetC3_AMP13_2: C3_AMP13.2 R6_AMP13.2 R20_AMP13.1 | length 75.9
  Top Layer w7: R6_AMP13.2@10261,5854.78 C3_AMP13.2@10293,5854.78 10293,5872 10287,5878 R20_AMP13.1@10287,5896.22
NetC3_AMP14_2: C3_AMP14.2 R6_AMP14.2 R20_AMP14.1 | length 75.9
  Top Layer w7: R6_AMP14.2@10627,5854.78 C3_AMP14.2@10659,5854.78 10659,5872 10653,5878 R20_AMP14.1@10653,5896.22
NetC3_AMP15_2: C3_AMP15.2 R6_AMP15.2 R20_AMP15.1 | length 75.9
  Top Layer w7: R6_AMP15.2@11095,5811.78 C3_AMP15.2@11127,5811.78 11127,5829 11121,5835 R20_AMP15.1@11121,5853.22
NetC3_AMP16_2: C3_AMP16.2 R6_AMP16.2 R20_AMP16.1 | length 75.9
  Top Layer w7: R6_AMP16.2@11517,5843.78 C3_AMP16.2@11549,5843.78 11549,5861 11543,5867 R20_AMP16.1@11543,5885.22
NetC3_AMP17_2: C3_AMP17.2 R6_AMP17.2 R20_AMP17.1 | length 75.9
  Top Layer w7: R6_AMP17.2@11905,5855.78 C3_AMP17.2@11937,5855.78 11937,5873 11931,5879 R20_AMP17.1@11931,5897.22
NetC3_AMP18_2: C3_AMP18.2 R6_AMP18.2 R20_AMP18.1 | length 75.9
  Top Layer w7: R6_AMP18.2@12361,5653.78 C3_AMP18.2@12393,5653.78 12393,5671 12387,5677 R20_AMP18.1@12387,5695.22
NetC3_AMP19_2: C3_AMP19.2 R6_AMP19.2 R20_AMP19.1 | length 75.9
  Top Layer w7: R6_AMP19.2@12753,5849.78 C3_AMP19.2@12785,5849.78 12785,5867 12779,5873 R20_AMP19.1@12779,5891.22
NetC3_AMP20_2: C3_AMP20.2 R6_AMP20.2 R20_AMP20.1 | length 75.9
  Top Layer w7: R6_AMP20.2@13243,5702.78 C3_AMP20.2@13275,5702.78 13275,5720 13269,5726 R20_AMP20.1@13269,5744.22
NetC3_AMP21_2: C3_AMP21.2 R6_AMP21.2 R20_AMP21.1 | length 75.9
  Top Layer w7: R6_AMP21.2@13793,5808.78 C3_AMP21.2@13825,5808.78 13825,5826 13819,5832 R20_AMP21.1@13819,5850.22
NetC3_AMP22_2: C3_AMP22.2 R6_AMP22.2 R20_AMP22.1 | length 75.9
  Top Layer w7: R6_AMP22.2@14498,5750.78 C3_AMP22.2@14530,5750.78 14530,5768 14524,5774 R20_AMP22.1@14524,5792.22
NetC3_AMP23_2: C3_AMP23.2 R6_AMP23.2 R20_AMP23.1 | length 75.9
  Top Layer w7: R6_AMP23.2@15307,5808.78 C3_AMP23.2@15339,5808.78 15339,5826 15333,5832 R20_AMP23.1@15333,5850.22
NetC3_AMP24_2: C3_AMP24.2 R6_AMP24.2 R20_AMP24.1 | length 75.9
  Top Layer w7: R6_AMP24.2@15765,5850.78 C3_AMP24.2@15797,5850.78 15797,5868 15791,5874 R20_AMP24.1@15791,5892.22
NetC3_AMP25_2: C3_AMP25.2 R6_AMP25.2 R20_AMP25.1 | length 75.9
  Top Layer w7: R6_AMP25.2@16264,5829.78 C3_AMP25.2@16296,5829.78 16296,5847 16290,5853 R20_AMP25.1@16290,5871.22
NetC3_AMP26_2: C3_AMP26.2 R6_AMP26.2 R20_AMP26.1 | length 75.9
  Top Layer w7: R6_AMP26.2@16721,5798.78 C3_AMP26.2@16753,5798.78 16753,5816 16747,5822 R20_AMP26.1@16747,5840.22
NetC3_AMP27_2: C3_AMP27.2 R6_AMP27.2 R20_AMP27.1 | length 75.9
  Top Layer w7: R6_AMP27.2@17251,5809.78 C3_AMP27.2@17283,5809.78 17283,5827 17277,5833 R20_AMP27.1@17277,5851.22
NetC3_AMP28_2: C3_AMP28.2 R6_AMP28.2 R20_AMP28.1 | length 75.9
  Top Layer w7: R6_AMP28.2@17782,5809.78 C3_AMP28.2@17814,5809.78 17814,5827 17808,5833 R20_AMP28.1@17808,5851.22
NetC3_AMP29_2: C3_AMP29.2 R6_AMP29.2 R20_AMP29.1 | length 75.9
  Top Layer w7: R6_AMP29.2@18199,5850.78 C3_AMP29.2@18231,5850.78 18231,5868 18225,5874 R20_AMP29.1@18225,5892.22
NetC3_AMP30_2: C3_AMP30.2 R6_AMP30.2 R20_AMP30.1 | length 75.9
  Top Layer w7: R6_AMP30.2@27317,5982.78 C3_AMP30.2@27349,5982.78 27349,6000 27343,6006 R20_AMP30.1@27343,6024.22
NetC4_AMP1_1: C4_AMP1.1 Q0_AMP1.3 R6_AMP1.1 | length 137.1
  Top Layer w7: C4_AMP1.1@1330,1596.22 R6_AMP1.1@1363,1596.22 ; Q0_AMP1.3@1365.34,1501.56 1365.34,1568.66 1363,1571 R6_AMP1.1@1363,1596.22 ; 1369,1590.22 R6_AMP1.1@1363,1596.22
NetC4_AMP1_2: C4_AMP1.2 Q1_AMP1.1 R2_AMP1.1 R3_AMP1.2 | length 660.4
  Top Layer w7: R3_AMP1.2@1276,1715.78 v1(1276,1776) ; R3_AMP1.2@1277.78,1714 1289,1714 ; 1292,1714 1330,1676 C4_AMP1.2@1330,1623.78 ; 1330,1666 R2_AMP1.1@1348.22,1666 ; v1@1365.34,2130.34 Q1_AMP1.1@1365.34,2191.6
  Bottom Layer w7: v1(1276,1776) 1276,1931 1259,1948 1259,1984 1364,2089 v1(1364,2129)
NetC4_AMP2_1: C4_AMP2.1 Q0_AMP2.3 R6_AMP2.1 | length 137.1
  Top Layer w7: C4_AMP2.1@1513,1596.22 R6_AMP2.1@1546,1596.22 ; Q0_AMP2.3@1548.34,1501.56 1548.34,1568.66 1546,1571 R6_AMP2.1@1546,1596.22 ; 1552,1590.22 R6_AMP2.1@1546,1596.22
NetC4_AMP2_2: C4_AMP2.2 Q1_AMP2.1 R2_AMP2.1 R3_AMP2.2 | length 660.4
  Top Layer w7: R3_AMP2.2@1459,1715.78 v1(1459,1776) ; R3_AMP2.2@1460.78,1714 1472,1714 ; 1475,1714 1513,1676 C4_AMP2.2@1513,1623.78 ; 1513,1666 R2_AMP2.1@1531.22,1666 ; v1@1548.34,2130.34 Q1_AMP2.1@1548.34,2191.6
  Bottom Layer w7: v1(1459,1776) 1459,1931 1442,1948 1442,1984 1547,2089 v1(1547,2129)
NetC4_AMP3_1: C4_AMP3.1 Q0_AMP3.3 R6_AMP3.1 | length 137.1
  Top Layer w7: C4_AMP3.1@1696,1596.22 R6_AMP3.1@1729,1596.22 ; Q0_AMP3.3@1731.34,1501.56 1731.34,1568.66 1729,1571 R6_AMP3.1@1729,1596.22 ; 1735,1590.22 R6_AMP3.1@1729,1596.22
NetC4_AMP3_2: C4_AMP3.2 Q1_AMP3.1 R2_AMP3.1 R3_AMP3.2 | length 660.4
  Top Layer w7: R3_AMP3.2@1642,1715.78 v1(1642,1776) ; R3_AMP3.2@1643.78,1714 1655,1714 ; 1658,1714 1696,1676 C4_AMP3.2@1696,1623.78 ; 1696,1666 R2_AMP3.1@1714.22,1666 ; v1@1731.34,2130.34 Q1_AMP3.1@1731.34,2191.6
  Bottom Layer w7: v1(1642,1776) 1642,1931 1625,1948 1625,1984 1730,2089 v1(1730,2129)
